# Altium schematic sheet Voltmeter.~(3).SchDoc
size A4
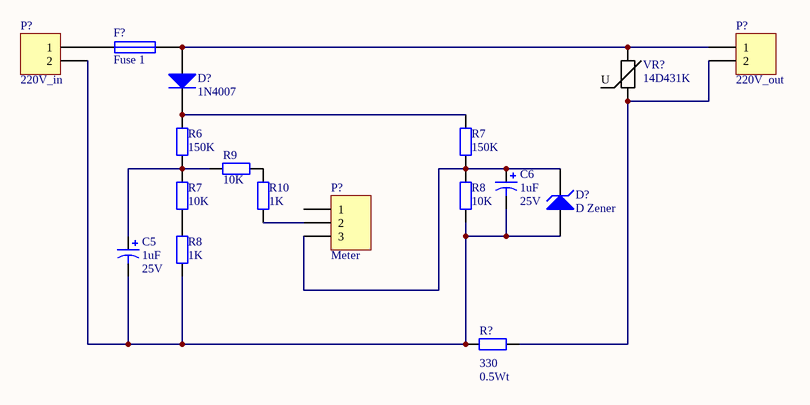
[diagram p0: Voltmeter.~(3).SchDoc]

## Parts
(Parts that share a designator on the sheet are numbered #1, #2 ... from top to bottom, then left to right.)
C5  25V  value 1uF  [RB7.6-15]
C6  25V  value 1uF  [RB7.6-15]
D?#1  1N4007  [DO-41]
D?#2  D Zener  [DIODE-0.7]
F?  Fuse 1  [PIN-W2/E2.8]
P?#1  220V_in  [HDR1X2]
P?#2  220V_out  [HDR1X2]
P?#3  Meter  [HDR1X3]
R6  value 150K  [AXIAL-0.4]  (hidden comment: Res2)
R7#1  value 150K  [AXIAL-0.4]  (hidden comment: Res2)
R7#2  value 10K  [AXIAL-0.4]  (hidden comment: Res2)
R8#1  value 10K  [AXIAL-0.4]  (hidden comment: Res2)
R8#2  value 1K  [AXIAL-0.4]  (hidden comment: Res2)
R9  value 10K  [AXIAL-0.4]  (hidden comment: Res2)
R10  value 1K  [AXIAL-0.4]  (hidden comment: Res2)
R?  0.5Wt  value 330  [AXIAL-0.4]
VR?  14D431K

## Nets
NetC5_1: C5.1 R6.1 R7#2.2 R9.2
NetC5_2: C5.2 C6.2 D?#2.1(A) P?#1.2 R8#1.1 R8#2.1 R?.1
NetC6_1: C6.1 D?#2.2(K) P?#3.3 R7#1.1 R8#1.2
NetD?#1_1: D?#1.1(A) F?.2 P?#2.1 VR?.1
NetD?#1_2: D?#1.2(K) R6.2 R7#1.2
NetF?_1: F?.1 P?#1.1
NetP?#2_2: P?#2.2 R?.2 VR?.2
NetP?#3_2: P?#3.2 R10.2
NetR7#2_1: R7#2.1 R8#2.2
NetR9_1: R9.1 R10.1

Not connected (* = marked no-connect by the designer): P?#3 1

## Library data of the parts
C5 C6 = Cap Pol1: Polarized Capacitor (Radial)
D?#1 = Diode 1N4007: 1 Amp General Purpose Rectifier
D?#2 = D Zener: Zener Diode
F? = Fuse 1: Fuse
P?#1 P?#2 = Header 2: Header, 2-Pin
P?#3 = Header 3: Header, 3-Pin
R6 R7#1 R7#2 R8#1 R8#2 R9 R10 R? = Res2: Resistor
VR? = Varistor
